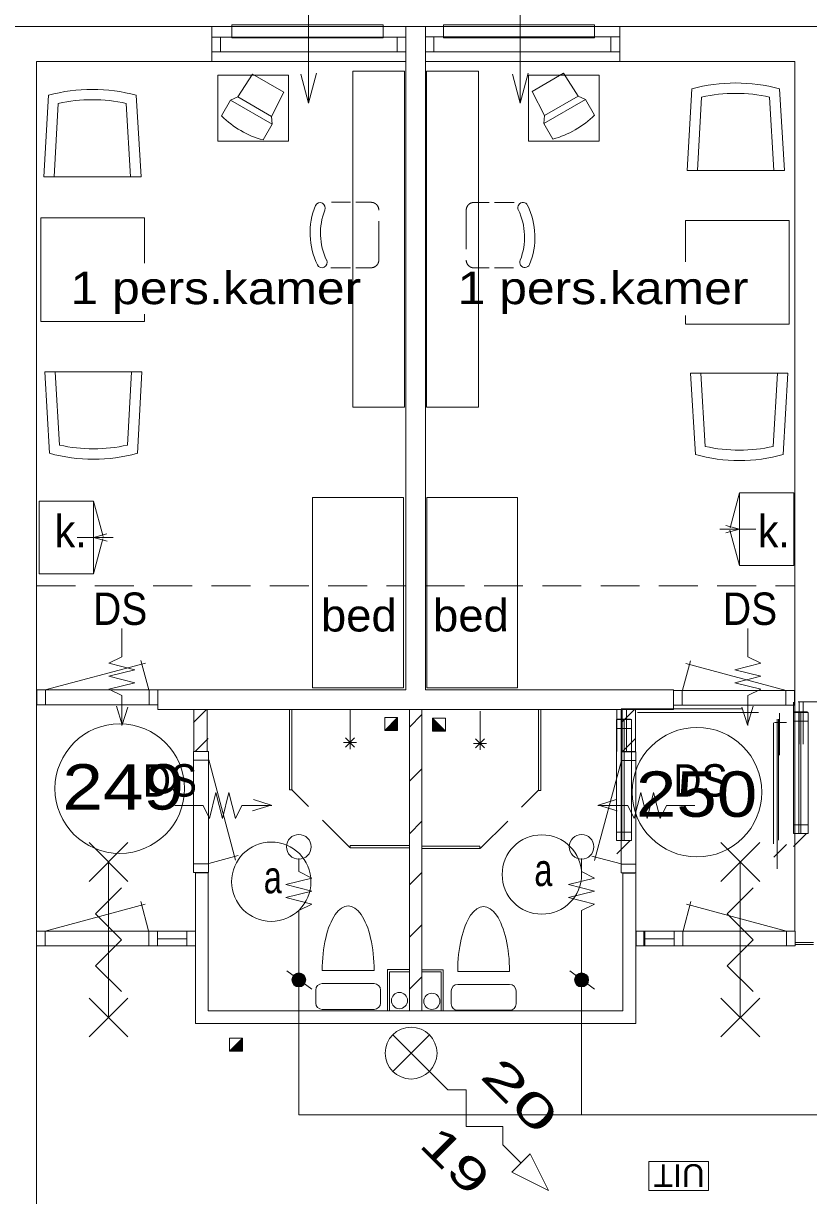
# Model space of a CAD drawing. Extents: x 295824 to 414724, y 24924 to 109024.
# Drawn here: x 301988 to 308047, y 95396 to 104442 of the extents above; entities that cross this region are included whole.
import ezdxf
from ezdxf.enums import TextEntityAlignment as Align

# ---------------------------------------------------------------- set-up
doc = ezdxf.new("R2010")
doc.units = 0
doc.header["$LTSCALE"] = 100
doc.linetypes.add('MEDIUM_DASHED', pattern=[4.5, 3, -1.5])
for name, color, linetype, lineweight in [('1', 7, 'Continuous', 13), ('16', 7, 'Continuous', 13), ('24', 7, 'Continuous', 13), ('61', 7, 'Continuous', 13)]:
    doc.layers.add(name, color=color, linetype=linetype, lineweight=lineweight)

msp = doc.modelspace()

# ---------------------------------------------------------------- hatches: boundary and pattern name
at = {"layer": '24'}
for points in [[(304167.9, 97060.5, 1), (304059.3, 97060.5, 1)], [(306349.9, 97060.5, 1), (306241.3, 97060.5, 1)]]:
    msp.add_hatch(color=256, dxfattribs=at).paths.add_polyline_path(points)
at = {"layer": '61'}
for points in [[(304776.2, 98986.3), (304876.2, 99086.3), (304876.2, 98986.3)], [(305244.4, 98979.7), (305144.4, 99079.7), (305144.4, 98979.7)], [(303578.3, 96509.7), (303678.3, 96609.7), (303678.3, 96509.7)]]:
    msp.add_hatch(color=256, dxfattribs=at).paths.add_polyline_path(points)

# ---------------------------------------------------------------- linework, layer by layer
at = {"layer": '1'}
for p, q in [((304113.6, 97029.2), (304113.6, 96018.7)), ((306295.6, 97022.5), (306295.6, 96018.7))]:
    msp.add_line(p, q, dxfattribs=at)
at = {"layer": '16'}
for p, q in [((302647.8, 99404.1), (302847.8, 99454.1)), ((307678.1, 99404.1), (307478.1, 99454.1)), ((303524.2, 98305.9), (303474.2, 98505.9)), ((306801.7, 98305.9), (306851.7, 98505.9))]:
    msp.add_line(p, q, dxfattribs=at)
at = {"layer": '24'}
for p, q in [((304188.6, 103826.9), (304129, 104049.3)), ((305820.9, 103826.9), (305761.3, 104049.3)), ((302751.2, 99028.7), (302706.2, 99172.8)), ((302793.6, 99164.5), (302751.2, 99028.7)), ((307532.3, 99164.5), (307574.7, 99028.7)), ((307574.7, 99028.7), (307619.8, 99172.8)), ((303763.9, 98451.7), (303899.7, 98409.3)), ((306562.1, 98451.7), (306426.3, 98409.3)), ((303899.7, 98409.3), (303755.5, 98364.2)), ((306426.3, 98409.3), (306570.5, 98364.2)), ((304113.6, 97545.9), (304113.6, 97006.4)), ((306295.6, 97545.9), (306295.6, 97037.5)), ((304022, 97131.3), (304213.6, 96989.6)), ((306204, 97131.3), (306395.5, 96989.6)), ((304113.6, 96018.7), (328710.3, 96018.7))]:
    msp.add_line(p, q, dxfattribs=at)
for points in [[(304188.6, 104801.9), (304188.6, 103826.9), (304250.3, 104057.1)], [(305820.9, 104801.9), (305820.9, 103826.9), (305882.6, 104057.1)], [(302847.8, 99454.1), (302647.8, 99504.1), (302747.8, 99554.1), (302747.8, 99772.8)], [(307478.1, 99454.1), (307678.1, 99504.1), (307578.1, 99554.1), (307578.1, 99772.8)], [(302747.8, 99022.8), (302747.8, 99254.1), (302647.8, 99304.1), (302847.8, 99354.1), (302647.8, 99404.1)], [(307578.1, 99022.8), (307578.1, 99254.1), (307678.1, 99304.1), (307478.1, 99354.1), (307678.1, 99404.1)], [(303474.2, 98505.9), (303424.2, 98305.9), (303374.2, 98405.9), (303155.5, 98405.9)], [(303905.5, 98405.9), (303674.2, 98405.9), (303624.2, 98305.9), (303574.2, 98505.9), (303524.2, 98305.9)], [(306420.5, 98405.9), (306651.7, 98405.9), (306701.7, 98305.9), (306751.7, 98505.9), (306801.7, 98305.9)], [(306851.7, 98505.9), (306901.7, 98305.9), (306951.7, 98405.9), (307170.5, 98405.9)], [(304113.6, 97995.9), (304113.6, 97895.9), (304213.6, 97845.9), (304013.6, 97795.9), (304213.6, 97745.9), (304013.6, 97695.9), (304213.6, 97645.9), (304113.6, 97595.9), (304113.6, 97545.9)], [(306295.6, 97995.9), (306295.6, 97895.9), (306395.6, 97845.9), (306195.6, 97795.9), (306395.6, 97745.9), (306195.6, 97695.9), (306395.6, 97645.9), (306295.6, 97595.9), (306295.6, 97545.9)]]:
    msp.add_lwpolyline(points, dxfattribs=at)
for points in [[(303597.3, 104331), (304763.2, 104331), (304763.2, 104431), (303597.3, 104431)], [(305229.6, 104331), (306395.5, 104331), (306395.5, 104431), (305229.6, 104431)]]:
    msp.add_lwpolyline(points, close=True, dxfattribs=at)
for centre, radius in [((304113.6, 98087.5), 95), ((306295.6, 98087.5), 95), ((304113.6, 97060.5), 54.3), ((306295.6, 97060.5), 54.3)]:
    msp.add_circle(centre, radius, dxfattribs=at)
at = {"layer": '61'}
for p, q in [((303441.2, 104147.5), (303441.2, 104417.5)), ((304940.1, 104416.2), (304940.1, 99297.6)), ((305090.1, 104416.2), (305090.1, 99297.6)), ((306589.5, 104147.6), (306589.5, 104417.6)), ((303508, 104223.4), (303508, 104337.2)), ((304873, 104222.8), (304873, 104336.8)), ((305156.5, 104223.7), (305156.5, 104337.7)), ((306520.9, 104223.4), (306520.9, 104337.1)), ((302090.1, 104147.6), (304940.1, 104147.6)), ((302090.1, 97436.8), (302090.1, 104147.6)), ((307940.1, 104147.6), (305090.1, 104147.6)), ((307940.1, 97436.4), (307940.1, 104147.6)), ((303756.2, 104051.5), (303642.5, 103874.6)), ((303998.7, 103911.5), (303756.2, 104051.5)), ((306156.6, 104057.7), (305914.1, 103917.7)), ((306156.6, 104057.7), (306270.2, 103880.8)), ((302145.9, 103258.4), (302180.9, 103887.7)), ((303642.5, 103874.6), (303587.2, 103848.8)), ((303998.7, 103911.5), (303902.3, 103724.6)), ((305914.1, 103917.7), (306010.4, 103730.8)), ((306005.1, 103670), (306325.5, 103855)), ((306395.5, 103733.7), (306325.5, 103855)), ((307110.4, 103307.6), (307145.3, 103936.9)), ((307190.5, 103307.6), (307221.9, 103873.5)), ((307746.7, 103873.4), (307780.2, 103307.6)), ((302226, 103258.4), (302257.4, 103824.3)), ((302782.2, 103824.2), (302815.7, 103258.4)), ((303587.2, 103848.8), (303517.3, 103727.8)), ((303587.2, 103848.8), (303907.6, 103663.8)), ((306010.4, 103730.8), (306005.1, 103670)), ((306005.1, 103670), (306075, 103549)), ((303837.6, 103542.5), (303907.6, 103663.8)), ((304512.2, 103061.4), (304366.1, 103061.4)), ((305776.3, 103060.5), (305623.9, 103060.5)), ((302923.2, 102592.3), (302923.2, 102941.9)), ((304359.7, 102556.4), (304512.2, 102556.4)), ((305623.9, 102555.5), (305770, 102555.5)), ((302123.2, 102141.9), (302923.2, 102141.9)), ((302923.2, 102141.9), (302923.2, 102198.9)), ((307097.5, 102189), (307097.5, 102122.2)), ((302266.4, 101187.6), (302232.9, 101753.4)), ((302822.6, 101753.4), (302791.2, 101187.5)), ((302902.7, 101753.4), (302867.8, 101124.1)), ((307250.5, 101177.8), (307217, 101743.6)), ((307806.7, 101743.6), (307775.3, 101177.7)), ((307886.9, 101743.6), (307851.9, 101114.3)), ((307513.3, 100819), (307441, 100549.1)), ((302529.4, 100753.9), (302602.4, 100481.2)), ((307639.2, 100539), (307363.2, 100539)), ((307513.3, 100539), (307409.5, 100566.8)), ((307513.3, 100539), (307409.9, 100511.3)), ((307513.3, 100259), (307440.2, 100531.7)), ((302403.5, 100473.9), (302679.5, 100473.9)), ((302529.4, 100473.9), (302632.8, 100501.6)), ((302529.4, 100473.9), (302633.2, 100446.1)), ((302529.4, 100193.9), (302601.7, 100463.8)), ((302955.3, 99299.1), (302894.5, 99525.9)), ((307075, 99295.4), (307135.8, 99522.2)), ((302156.8, 99298.4), (302929.6, 99505.5)), ((307873.5, 99294.8), (307100.7, 99501.8)), ((302157.6, 99183.8), (302157.6, 99297.8)), ((302957.6, 99183.8), (302957.6, 99297.8)), ((303024.6, 99183.8), (303024.6, 99297.8)), ((304940.1, 99297.6), (303025.4, 99297.6)), ((303025.4, 99297.6), (303025.4, 99147.6)), ((305090.1, 99297.6), (307004.9, 99297.6)), ((307004.9, 99297.6), (307004.9, 99147.6)), ((307005.7, 99180.1), (307005.7, 99294.1)), ((307072.7, 99180.1), (307072.7, 99294.1)), ((307872.7, 99180.1), (307872.7, 99294.1)), ((303025.4, 99147.6), (303315.1, 99147.6)), ((307004.9, 99147.6), (303025.4, 99147.6)), ((303301.8, 99046.8), (303401.5, 99146.5)), ((303407.4, 98824.2), (303407.4, 99147)), ((304058.7, 99148.6), (304058.7, 98528.1)), ((304966.4, 99147.6), (304966.4, 96822.6)), ((305062.7, 99147.6), (305062.7, 96822.6)), ((306567.3, 98823), (306567.3, 99147)), ((307536, 99151.2), (306602, 99151.2)), ((306602.2, 98823), (306602.2, 99147)), ((306602.2, 99147), (306712.2, 99147)), ((306603.9, 99046.8), (306703.6, 99146.5)), ((306606, 99149), (306720, 99149)), ((306610, 98823), (306610, 99147)), ((306642.2, 98824.2), (306642.2, 99148.3)), ((306712.2, 98823), (306712.2, 99147)), ((307931.5, 98878.7), (307931.5, 99202.8)), ((308900.2, 99206.9), (307966.2, 99206.9)), ((307974.2, 98878.7), (307974.2, 99202.8)), ((308006.5, 98879.9), (308006.5, 99204)), ((304508.5, 98942.1), (304508.5, 99142.1)), ((304966.9, 99011.5), (305062.7, 99107.3)), ((305512.1, 98935.5), (305512.1, 99135.5)), ((305961.9, 99142), (305961.9, 98521.5)), ((306673.9, 99072.1), (306568.6, 99072.1)), ((306607.4, 98136.1), (306607.4, 99068.5)), ((306623.2, 98136.1), (306623.2, 99068.5)), ((306679.9, 98136.1), (306679.9, 99068.5)), ((307660.1, 99123.3), (306726.1, 99123.3)), ((307804.5, 98138.8), (307804.5, 99072.8)), ((307815.5, 98138.8), (307815.5, 99072.8)), ((307822.7, 98795.1), (307822.7, 99119.2)), ((308044.1, 99057.2), (307930.1, 99057.2)), ((308038.1, 99127.8), (307932.9, 99127.8)), ((307971.6, 98191.8), (307971.6, 99124.2)), ((307987.4, 98191.8), (307987.4, 99124.2)), ((308044.1, 98191.8), (308044.1, 99124.2)), ((306679.9, 99001.5), (306565.9, 99001.5)), ((307775.7, 98110.9), (307775.7, 99044.9)), ((307877.9, 99045.7), (307783.2, 99045.7)), ((303314.1, 98824.2), (303413.8, 98923.9)), ((304558.5, 98892.1), (304458.5, 98892.1)), ((304543.9, 98927.4), (304473.1, 98856.7)), ((304543.9, 98856.7), (304473.1, 98927.4)), ((304508.5, 98942.1), (304508.5, 98842.1)), ((305462.1, 98885.5), (305562.1, 98885.5)), ((305476.7, 98920.9), (305547.4, 98850.2)), ((305476.7, 98850.2), (305547.4, 98920.9)), ((305512.1, 98935.5), (305512.1, 98835.5)), ((306612.5, 98824.2), (306712.2, 98923.9)), ((303303.3, 98823), (303413.2, 98823)), ((306601.5, 98819.4), (306715.5, 98819.4)), ((306602.2, 98823), (306712.2, 98823)), ((306714.9, 98819.4), (306714.9, 97885.4)), ((307806, 98850), (307806, 97917.6)), ((303301.5, 98756.7), (303415.5, 98756.7)), ((303418.6, 98757.4), (303625.7, 97984.7)), ((306602.9, 98753.2), (306395.8, 97980.5)), ((306714.9, 98752.4), (306600.9, 98752.4)), ((304966.9, 98593.4), (305062.7, 98689.2)), ((304046.5, 98526.9), (304064.5, 98526.9)), ((304966.9, 98188.8), (305062.7, 98284.6)), ((308044.1, 98257.2), (307930.1, 98257.2)), ((306679.9, 98201.5), (306565.9, 98201.5)), ((306715.1, 98215), (306715.1, 97322.7)), ((308031.5, 98189.7), (307931.8, 98090)), ((308042.3, 98190.9), (307932.3, 98190.9)), ((302794.8, 98119.9), (302494.8, 97819.9)), ((302494.8, 98119.9), (302794.8, 97819.9)), ((304966.4, 98098.6), (304509.5, 98098.6)), ((304509.5, 98080.6), (304509.5, 98098.6)), ((304966.4, 98080.6), (304509.5, 98080.6)), ((305061.5, 98074), (305511, 98074)), ((305061.9, 98092), (305511, 98092)), ((305511, 98074), (305511, 98092)), ((306667.2, 98134), (306567.5, 98034.3)), ((306678, 98135.2), (306568.1, 98135.2)), ((307670.3, 98119.9), (307370.3, 97819.9)), ((307370.3, 98119.9), (307670.3, 97819.9)), ((307878.1, 98106.1), (307778.4, 98006.4)), ((302644.8, 96769.9), (302644.8, 97969.9)), ((303419.3, 97959), (303646.1, 98019.8)), ((306602.2, 97954.8), (306375.4, 98015.6)), ((307520.3, 96769.9), (307520.3, 97969.9)), ((303301.5, 97956.7), (303415.5, 97956.7)), ((303315.1, 97886.1), (303315.1, 97437.5)), ((303315.1, 97886.1), (303412.7, 97886.1)), ((304966.9, 97792.8), (305062.7, 97888.6)), ((306714.9, 97952.4), (306600.9, 97952.4)), ((306612.7, 97884.6), (306612.7, 96822.6)), ((306612.7, 97884.6), (306707.4, 97884.6)), ((302155.5, 97437.3), (302928.3, 97644.4)), ((302953.9, 97437.9), (302893.2, 97664.8)), ((307078.8, 97437.9), (307139.5, 97664.8)), ((307877.2, 97437.3), (307104.4, 97644.4)), ((302156.3, 97322.7), (302156.3, 97436.7)), ((302956.3, 97322.7), (302956.3, 97436.7)), ((303023.3, 97322.7), (303023.3, 97436.7)), ((303249.3, 97322.7), (303249.3, 97436.7)), ((304966.9, 97389.4), (305062.7, 97485.2)), ((306775.9, 97322.7), (306775.9, 97436.7)), ((306783.4, 97322.7), (306783.4, 97436.7)), ((307009.4, 97322.7), (307009.4, 97436.7)), ((307076.4, 97322.7), (307076.4, 97436.7)), ((307876.4, 97322.7), (307876.4, 97436.7)), ((303249.3, 97376.8), (303023.3, 97376.8)), ((306783.4, 97376.8), (307009.4, 97376.8)), ((307944.7, 97348.9), (308085.9, 97348.9)), ((302090.1, 94558.1), (302090.1, 97322)), ((307944.7, 97333.9), (308085.9, 97333.9)), ((304694.2, 97131.8), (304294.2, 97131.8)), ((304797.6, 96823.1), (304797.6, 97139.3)), ((304797.6, 97139.3), (304965.6, 97139.3)), ((304812.6, 97123.1), (304965, 97123.1)), ((304812.6, 96823.1), (304812.6, 97123.1)), ((304966.9, 96988.5), (305062.7, 97084.3)), ((305062.7, 97122.6), (305212.7, 97122.6)), ((305212.7, 97122.6), (305212.7, 96822.6)), ((305739.5, 97125.6), (305339.5, 97125.6)), ((304244.2, 96881.8), (304244.2, 96981.8)), ((304294.2, 97031.8), (304694.2, 97031.8)), ((304744.2, 96981.8), (304744.2, 96881.8)), ((305289.5, 96875.6), (305289.5, 96975.6)), ((305339.5, 97025.6), (305739.5, 97025.6)), ((305789.5, 96975.6), (305789.5, 96875.6)), ((302794.8, 96919.9), (302494.8, 96619.9)), ((302494.8, 96919.9), (302794.8, 96619.9)), ((307670.3, 96919.9), (307370.3, 96619.9)), ((307370.3, 96919.9), (307670.3, 96619.9)), ((304694.2, 96831.8), (304294.2, 96831.8)), ((305739.5, 96825.6), (305339.5, 96825.6)), ((305121.5, 96636.6), (304838.6, 96353.8))]:
    msp.add_line(p, q, dxfattribs=at)
at = {"layer": '61', "linetype": 'MEDIUM_DASHED'}
for p, q in [((304670.8, 103061.4), (304554.5, 103061.4)), ((305581.5, 103060.5), (305465.3, 103060.5)), ((304730.8, 102616.4), (304730.8, 103001.4)), ((305405.3, 103000.5), (305405.3, 102615.5)), ((304554.5, 102556.4), (304670.8, 102556.4)), ((305465.3, 102555.5), (305581.5, 102555.5)), ((302090.1, 100101), (304939.8, 100101)), ((305093, 100101), (307940.7, 100101)), ((304507.5, 98081), (304060.6, 98527.9)), ((305513.1, 98074.4), (305960, 98521.3))]:
    msp.add_line(p, q, dxfattribs=at)
at = {"layer": '61'}
for points in [[(301796.6, 92184.5), (301820.1, 104417.6), (332210.1, 104417.6)], [(302858.6, 103887.7), (302895.9, 103258.4), (302145.9, 103258.4)], [(303642.5, 103874.6), (303902.3, 103724.6), (303907.6, 103663.8)], [(306010.4, 103730.8), (306270.2, 103880.8), (306325.5, 103855)], [(307823.1, 103936.8), (307860.3, 103307.6), (307110.4, 103307.6)], [(302923.2, 102941.9), (302123.2, 102941.9), (302123.2, 102141.9)], [(307097.5, 102122.2), (307897.5, 102122.2), (307897.5, 102922.2), (307097.5, 102922.2), (307097.5, 102602.1)], [(302190, 101124.2), (302152.8, 101753.4), (302902.7, 101753.4)], [(307174.1, 101114.3), (307136.9, 101743.6), (307886.9, 101743.6)], [(302090.6, 99183.8), (302090.6, 99297.8), (303024.6, 99297.8)], [(303024.6, 99183.8), (302090.6, 99183.8), (302090.6, 99297.8)], [(307939.7, 99180.1), (307939.7, 99294.1), (307005.7, 99294.1)], [(307005.7, 99180.1), (307939.7, 99180.1), (307939.7, 99294.1)], [(303303.3, 98823), (303303.3, 99147), (303407.4, 99147)], [(304040.7, 99148.6), (304040.7, 98528.1), (304058.7, 98528.1)], [(304876.2, 99086.3), (304876.2, 98986.3), (304776.2, 98986.3)], [(305144.4, 99079.7), (305144.4, 98979.7), (305244.4, 98979.7)], [(305979.9, 99142), (305979.9, 98521.5), (305961.9, 98521.5)], [(303412.7, 97886.1), (303412.7, 96822.6), (306612.7, 96822.6)], [(302744.8, 96969.9), (302544.8, 97169.9), (302744.8, 97369.9), (302544.8, 97569.9), (302744.8, 97769.9)], [(307620.3, 96969.9), (307420.3, 97169.9), (307620.3, 97369.9), (307420.3, 97569.9), (307620.3, 97769.9)], [(303315.1, 97322), (303315.1, 96722.6), (306715.1, 96722.6), (306715.1, 97322.6)], [(305062.7, 97137.6), (305227.7, 97137.6), (305227.7, 96822.6)], [(304838.6, 96636.6), (305262.9, 96212.3), (305404.3, 96212.3), (305404.3, 95929.5), (305687.1, 95929.5), (305687.1, 95788.1), (305828.6, 95646.7)], [(303678.3, 96609.7), (303678.3, 96509.7), (303578.3, 96509.7)]]:
    msp.add_lwpolyline(points, dxfattribs=at)
for points in [[(303441.2, 104223.2), (303441.2, 104337.2), (304939.9, 104337.2), (304939.9, 104223.2)], [(305090.2, 104223.4), (305090.2, 104337.4), (306589.6, 104337.4), (306589.6, 104223.4)], [(304033.8, 104041.8), (303487.6, 104041.8), (303487.6, 103533.7), (304033.8, 103533.7)], [(304529.6, 101480.4), (304529.6, 104072.3), (304929.6, 104072.3), (304929.6, 101480.4)], [(305099.7, 101480.4), (305099.7, 104072.3), (305499.7, 104072.3), (305499.7, 101480.4)], [(306432.5, 104041.8), (305886.3, 104041.8), (305886.3, 103533.7), (306432.5, 103533.7)], [(304220.2, 99313.9), (304920.2, 99313.9), (304920.2, 100783.9), (304220.2, 100783.9)], [(305100.1, 99313.9), (305800.1, 99313.9), (305800.1, 100783.9), (305100.1, 100783.9)], [(307933.3, 100819), (307513.3, 100819), (307513.3, 100259), (307933.3, 100259)], [(302109.4, 100193.9), (302529.4, 100193.9), (302529.4, 100753.9), (302109.4, 100753.9)], [(304876.2, 99086.3), (304776.2, 99086.3), (304776.2, 98986.3)], [(304776.2, 98986.3), (304876.2, 99086.3), (304876.2, 98986.3)], [(305144.4, 99079.7), (305244.4, 99079.7), (305244.4, 98979.7)], [(305244.4, 98979.7), (305144.4, 99079.7), (305144.4, 98979.7)], [(306679.9, 99069.4), (306565.9, 99069.4), (306565.9, 98135.4), (306679.9, 98135.4)], [(308044.1, 99125.2), (307930.1, 99125.2), (307930.1, 98191.2), (308044.1, 98191.2)], [(303301.5, 97888.7), (303415.5, 97888.7), (303415.5, 98822.7), (303301.5, 98822.7)], [(306714.9, 98819.4), (306714.9, 97885.4), (306600.9, 97885.4), (306600.9, 98819.4)], [(302089.3, 97322.7), (302089.3, 97436.7), (303315.7, 97436.7), (303315.7, 97322.7)], [(302089.3, 97322.7), (302089.3, 97436.7), (303315.7, 97436.7), (303315.7, 97322.7)], [(306716.4, 97322.7), (306716.4, 97436.7), (307943.4, 97436.7), (307943.4, 97322.7)], [(303678.3, 96609.7), (303578.3, 96609.7), (303578.3, 96509.7)], [(303578.3, 96509.7), (303678.3, 96609.7), (303678.3, 96509.7)], [(305757.9, 95575.9), (305899.3, 95717.4), (306040.7, 95434.5)], [(307273.8, 95659.3), (306814.1, 95659.3), (306814.1, 95434.7), (307273.8, 95434.7)]]:
    msp.add_lwpolyline(points, close=True, dxfattribs=at)
for centre, radius in [((302731.4, 98536.8), 500), ((307186, 98509), 500), ((305989, 97873.7), 306.3), ((303900.9, 97817.9), 306.3), ((304890.2, 96900.6), 62.5), ((305140.2, 96895), 62.5), ((304980, 96495.2), 200)]:
    msp.add_circle(centre, radius, dxfattribs=at)
for centre, radius, start, end in [((307484.1, 102697.1), 1285.2, 74.70731, 105.28507), ((302519.7, 102648), 1285.2, 74.70731, 105.28507), ((302519.7, 102648), 1205.2, 77.41626, 102.56606), ((307484.1, 102697.1), 1205.2, 77.41626, 102.56606), ((304031.6, 104247.1), 730.8, 225.27982, 254.60839), ((305882.4, 104254), 730.8, 285.27982, 314.60839), ((304765.8, 102824.6), 565.2, 157.99711, 205.84523), ((304277.7, 103019), 40, 334.24441, 154.24441), ((305843.4, 103020.5), 40, 25.75559, 205.75559), ((305370.3, 102792.3), 565.2, 337.99711, 25.84523), ((304765.8, 102824.6), 485.2, 158.65343, 205.61348), ((305370.3, 102792.3), 485.2, 338.65343, 25.61348), ((304292.7, 102596.4), 40, 205.75559, 25.75559), ((305858.3, 102597.9), 40, 154.24441, 334.24441), ((302528.9, 102363.9), 1205.2, 257.41626, 282.56606), ((307513.1, 102354), 1205.2, 257.41626, 282.56606), ((302528.9, 102363.9), 1285.2, 254.70731, 285.28507), ((307513.1, 102354), 1285.2, 254.70731, 285.28507), ((304294.2, 96981.8), 50, 90, 180), ((304694.2, 96981.8), 50, 0, 90), ((305339.5, 96975.6), 50, 90, 180), ((305739.5, 96975.6), 50, 0, 90), ((304294.2, 96881.8), 50, 180, 270), ((304694.2, 96881.8), 50, 270, 0), ((305339.5, 96875.6), 50, 180, 270), ((305739.5, 96875.6), 50, 270, 0)]:
    msp.add_arc(centre, radius, start, end, dxfattribs=at)
at = {"layer": '61', "linetype": 'MEDIUM_DASHED'}
for centre, start, end in [((304670.8, 103001.4), 0, 90), ((305465.3, 103000.5), 90, 180), ((304670.8, 102616.4), 270, 0), ((305465.3, 102615.5), 180, 270)]:
    msp.add_arc(centre, 60, start, end, dxfattribs=at)
at = {"layer": '61'}
for centre in [(304494.2, 97131.8), (305539.5, 97125.6)]:
    msp.add_ellipse(centre, major_axis=(0, 500), ratio=0.4, start_param=4.712389, end_param=7.853982, dxfattribs=at)

# ---------------------------------------------------------------- texts
at = {"layer": '24', "width": 0.9}
for p in [(302526, 99799.9), (307386.6, 99799.9), (302909.1, 98474.9), (307003.5, 98474.9)]:
    msp.add_text('DS', height=250, dxfattribs=at).set_placement(p)
at = {"layer": '61'}
for s, width, p in [('1 pers.kamer', 1.15, (302351.6, 102275.4)), ('1 pers.kamer', 1.15, (305339.5, 102275.4)), ('k.', 0.95, (302229.1, 100398.6)), ('k.', 0.95, (307655.7, 100398.6)), ('bed', 1.05, (304283.8, 99749.1)), ('bed', 1.05, (305148.9, 99749.1)), ('a', 0.75, (305931, 97784.5)), ('a', 0.75, (303842.9, 97728.8))]:
    msp.add_text(s, height=250, dxfattribs=dict(at, width=width)).set_placement(p)
at = {"layer": '61', "width": 1.2}
for s, p in [('249', (302757.7, 98374.8)), ('250', (307183, 98319.1))]:
    msp.add_text(s, height=350, dxfattribs=at).set_placement(p, align=Align.CENTER)
at = {"layer": '61'}
for s, height, rotation, width, p in [('20', 250, 315, 1.75, (305502.6, 96310)), ('19', 250, 315, 1.55, (305030.3, 95781.5)), ('UIT', 175, 180, 1.05, (307247, 95637.9))]:
    msp.add_text(s, height=height, rotation=rotation, dxfattribs=dict(at, width=width)).set_placement(p)

doc.saveas('drawing.dxf')
